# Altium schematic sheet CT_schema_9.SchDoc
size 382 x 278 mm
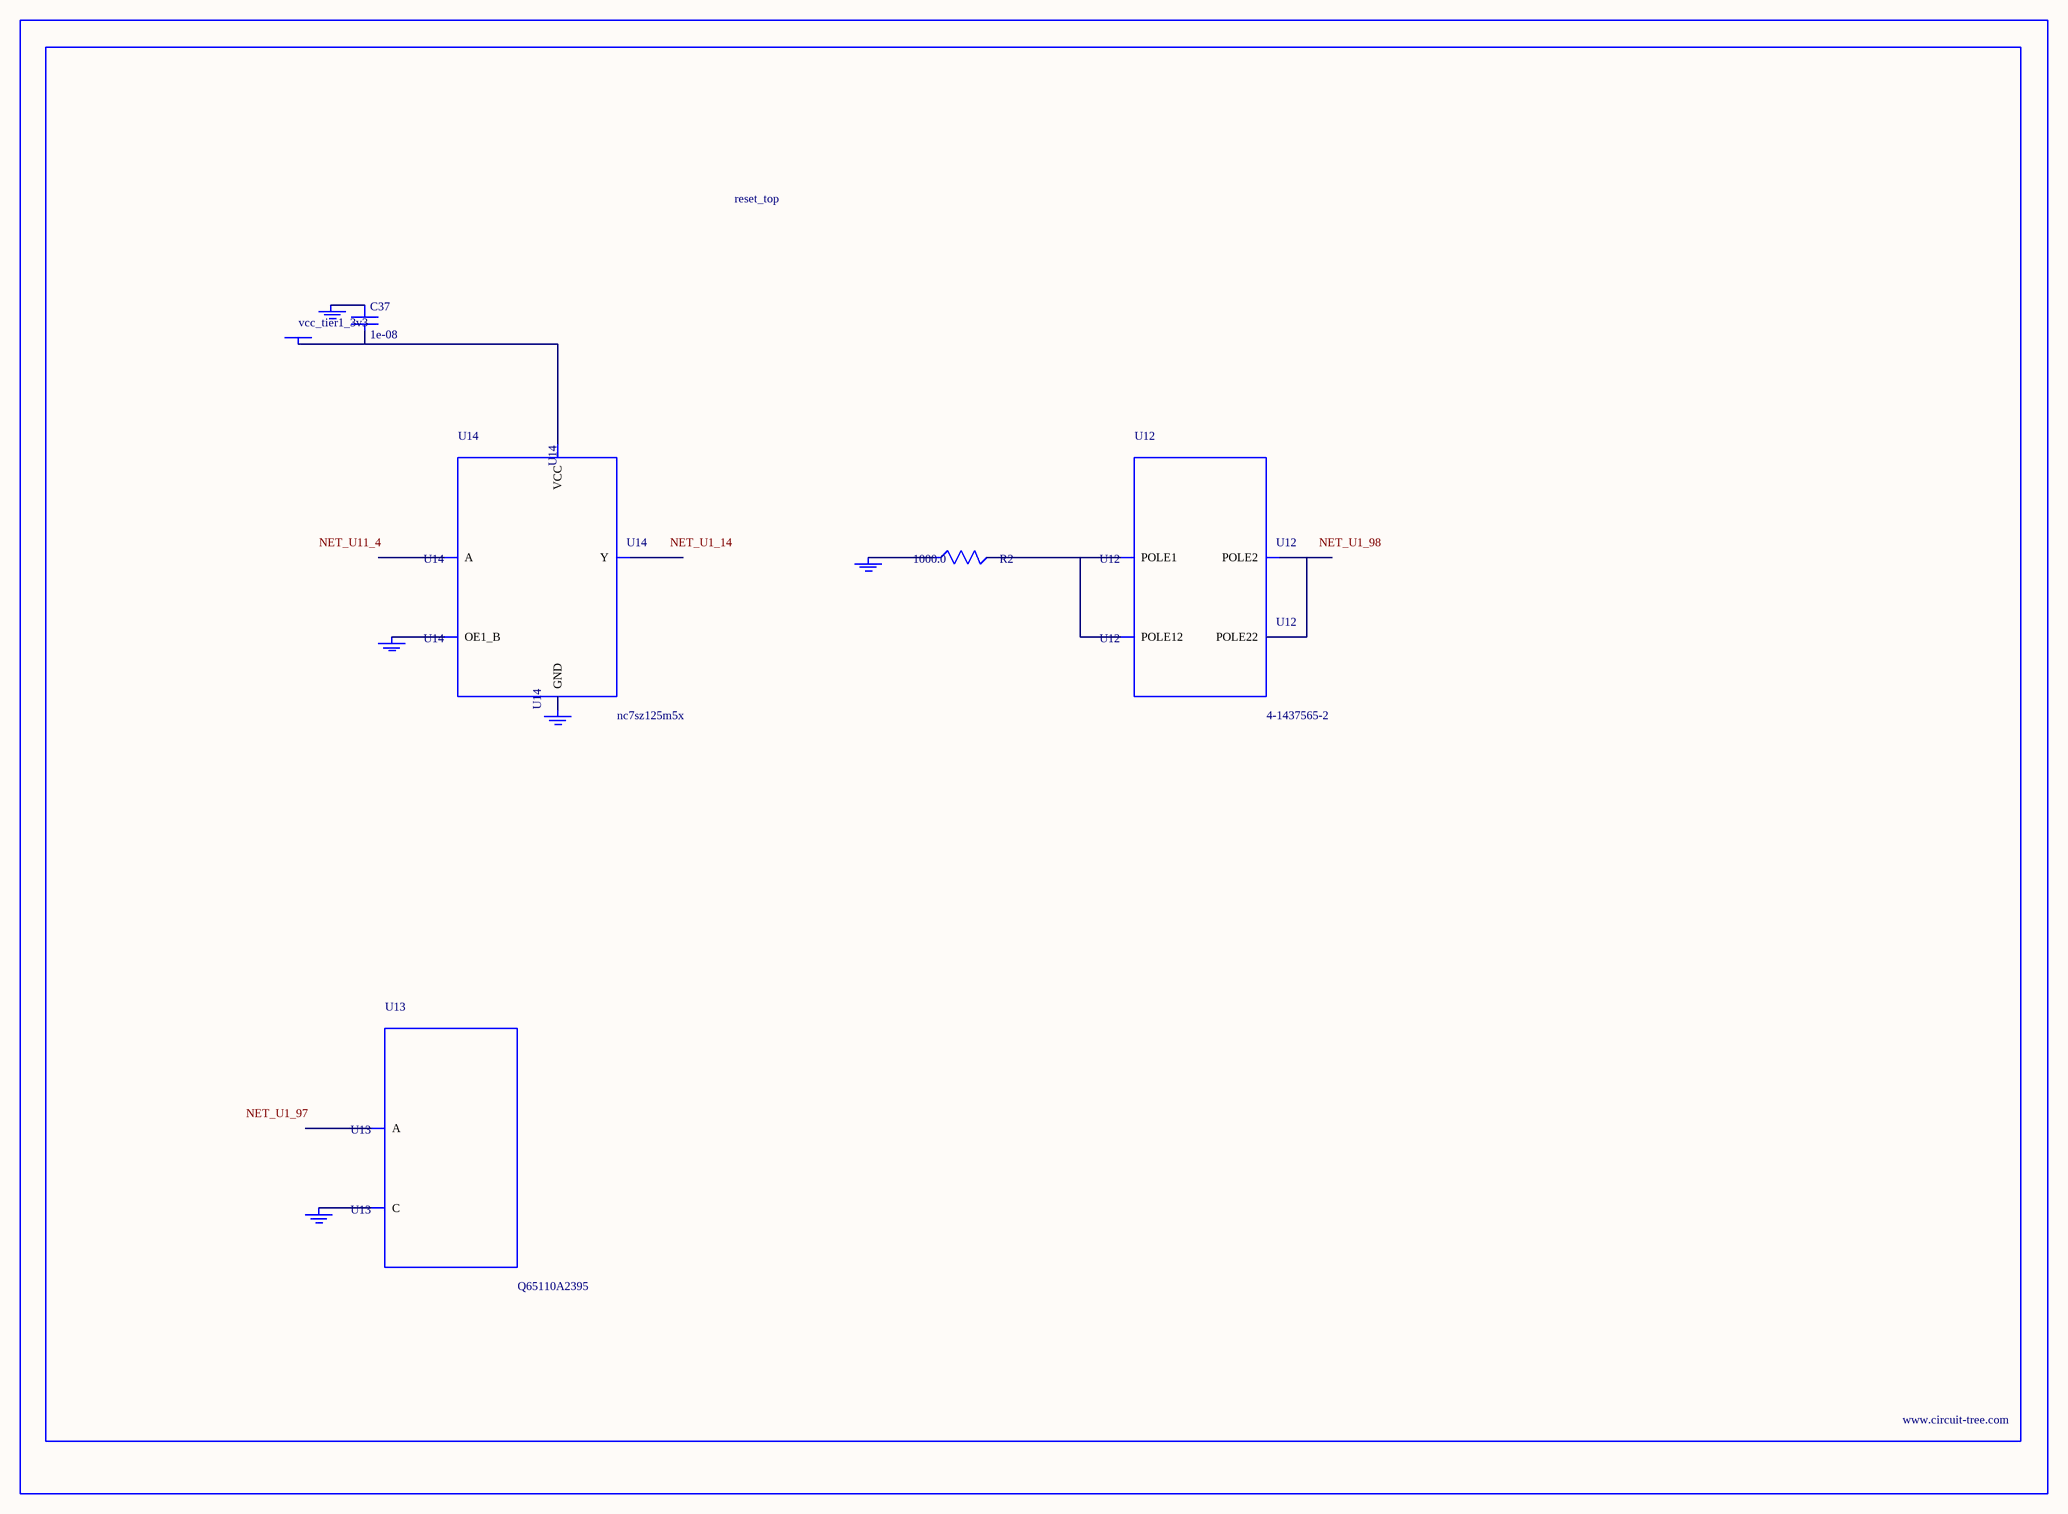
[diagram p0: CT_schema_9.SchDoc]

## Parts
BORDER8  (no value)
C37  1e-08  [C0402]
GND_INSTANCE_8_0  (no value)
GND_INSTANCE_8_1  (no value)
GND_INSTANCE_8_2  (no value)
GND_INSTANCE_8_3  (no value)
GND_INSTANCE_8_4  (no value)
POWER_INSTANCE_8_0  vcc_tier1_3v3
R2  1000.0  [R0603]
U12  4-1437565-2  [SW_4-1437565-2]
U13  Q65110A2395  [LGM67K-G1J2-24-Z]
U14  nc7sz125m5x  [NC7SZ125M5X]

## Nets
NetC37_1: C37.1 GND_INSTANCE_8_2.0(GND)
NetC37_2: C37.2 POWER_INSTANCE_8_0.0(PWR) U14.5(VCC)
NetGND_INSTANCE_8_0_0: GND_INSTANCE_8_0.0(GND) R2.1
NetGND_INSTANCE_8_1_0: GND_INSTANCE_8_1.0(GND) U13.C
NetGND_INSTANCE_8_3_0: GND_INSTANCE_8_3.0(GND) U14.1(OE1_B)
NetGND_INSTANCE_8_4_0: GND_INSTANCE_8_4.0(GND) U14.3(GND)
NetR2_2: R2.2 U12.1(POLE1) U12.2(POLE12)
NetU12_3: U12.3(POLE2) U12.4(POLE22)

Not connected (* = marked no-connect by the designer): U13 A; U14 2(A) 4(Y)

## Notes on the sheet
- Labels drawn without touching a wire or pin: NET_U1_14, NET_U1_97, NET_U1_98, NET_U11_4

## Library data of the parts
BORDER8 = BORDER_PAGE8
C37 = C0402C103K3RAC
GND_INSTANCE_8_0-GND_INSTANCE_8_4 = GND
POWER_INSTANCE_8_0 = PWR
R2 = RC0603JR-071KL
